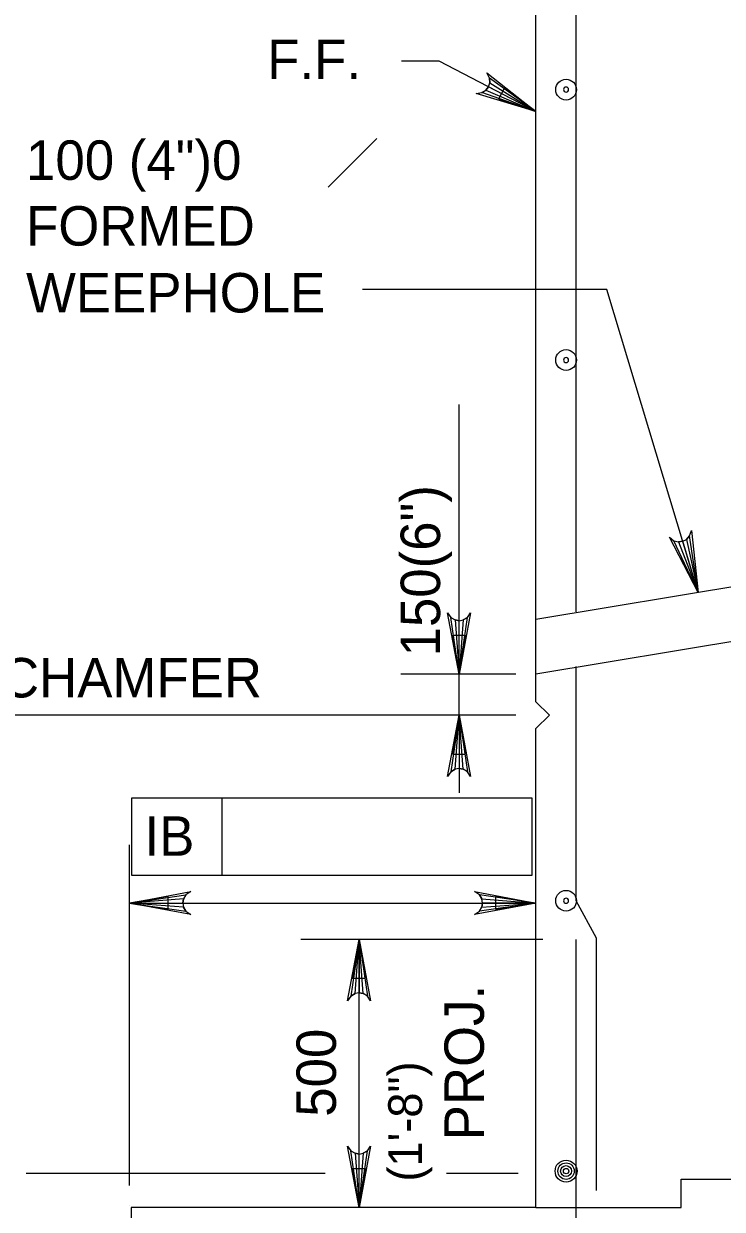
# Model space of a CAD drawing. Extents: x 638340 to 640241, y 295465 to 298435.
# Drawn here: x 639055.2 to 639108.3, y 297631.5 to 297721.6 of the extents above; entities that cross this region are included whole.
import ezdxf

# ---------------------------------------------------------------- set-up
doc = ezdxf.new("R2010")
doc.units = 0
for name, color, linetype in [('3', 7, 'Continuous'), ('4', 7, 'Continuous'), ('5', 7, 'Continuous'), ('6', 7, 'Continuous'), ('7', 7, 'Continuous'), ('9', 7, 'Continuous')]:
    doc.layers.add(name, color=color, linetype=linetype)

# ---------------------------------------------------------------- blocks, each defined once
blk = doc.blocks.new('B')
at = {"layer": '3'}
blk.add_circle((0, 0), 0.16, dxfattribs=at)
for start, end in [(0, 180), (180, 0)]:
    blk.add_arc((0, 0), 0.0391, start, end, dxfattribs=at)

msp = doc.modelspace()

# ---------------------------------------------------------------- linework, layer by layer
at = {"layer": '3'}
for p, q in [((639086.814, 297718.756), (639083.955, 297718.756)), ((639094.166, 297714.945), (639086.814, 297718.756)), ((639078.382, 297709.182), (639082.07, 297712.87)), ((639088.328, 297672.152), (639088.328, 297692.661)), ((639088.328, 297675.104), (639088.328, 297678.058)), ((639092.628, 297672.152), (639083.899, 297672.152)), ((639088.328, 297669.031), (639088.328, 297672.152)), ((639092.628, 297669.031), (639042.903, 297669.031)), ((639087.607, 297669.031), (639083.899, 297669.031)), ((639088.328, 297669.031), (639088.328, 297663.126)), ((639063.465, 297662.758), (639093.843, 297662.758)), ((639063.465, 297656.853), (639063.465, 297662.758)), ((639070.311, 297656.853), (639070.311, 297662.758)), ((639093.843, 297662.758), (639093.843, 297656.853)), ((639093.843, 297656.853), (639063.465, 297656.853)), ((639094.678, 297651.978), (639076.301, 297651.978)), ((639080.73, 297631.6), (639080.73, 297651.978)), ((639078.157, 297634.174), (639055.421, 297634.174)), ((639092.816, 297634.174), (639087.378, 297634.174))]:
    msp.add_line(p, q, dxfattribs=at)
for points in [[(639094.166, 297714.945), (639089.626, 297716.314), (639090.059, 297716.37), (639090.368, 297716.562), (639090.56, 297716.814), (639090.655, 297717.116), (639090.635, 297717.479), (639090.43, 297717.866), (639094.166, 297714.945), (639090.635, 297717.479), (639090.655, 297717.116), (639094.166, 297714.945), (639090.56, 297716.814), (639090.368, 297716.562), (639094.166, 297714.945), (639090.059, 297716.37)], [(639088.328, 297672.152), (639087.455, 297676.812), (639087.703, 297676.454), (639088.016, 297676.269), (639088.328, 297676.214), (639088.641, 297676.269), (639088.953, 297676.454), (639089.201, 297676.812), (639088.328, 297672.152), (639088.953, 297676.454), (639088.641, 297676.269), (639088.328, 297672.152), (639088.328, 297676.214), (639088.016, 297676.269), (639088.328, 297672.152), (639087.703, 297676.454)], [(639088.328, 297669.031), (639089.201, 297664.37), (639088.953, 297664.728), (639088.641, 297664.914), (639088.328, 297664.968), (639088.016, 297664.914), (639087.703, 297664.728), (639087.455, 297664.37), (639088.328, 297669.031), (639087.703, 297664.728), (639088.016, 297664.914), (639088.328, 297669.031), (639088.328, 297664.968), (639088.641, 297664.914), (639088.328, 297669.031), (639088.953, 297664.728)], [(639063.269, 297654.743), (639067.929, 297655.616), (639067.571, 297655.368), (639067.386, 297655.055), (639067.331, 297654.743), (639067.386, 297654.43), (639067.571, 297654.118), (639067.929, 297653.87), (639063.269, 297654.743), (639067.571, 297654.118), (639067.386, 297654.43), (639063.269, 297654.743), (639067.331, 297654.743), (639067.386, 297655.055), (639063.269, 297654.743), (639067.571, 297655.368)], [(639094.166, 297654.743), (639089.505, 297653.87), (639089.864, 297654.118), (639090.049, 297654.43), (639090.103, 297654.743), (639090.049, 297655.055), (639089.864, 297655.368), (639089.505, 297655.616), (639094.166, 297654.743), (639089.864, 297655.368), (639090.049, 297655.055), (639094.166, 297654.743), (639090.103, 297654.743), (639090.049, 297654.43), (639094.166, 297654.743), (639089.864, 297654.118)], [(639080.73, 297651.978), (639081.603, 297647.317), (639081.355, 297647.676), (639081.042, 297647.861), (639080.73, 297647.915), (639080.417, 297647.861), (639080.105, 297647.676), (639079.857, 297647.317), (639080.73, 297651.978), (639080.105, 297647.676), (639080.417, 297647.861), (639080.73, 297651.978), (639080.73, 297647.915), (639081.042, 297647.861), (639080.73, 297651.978), (639081.355, 297647.676)], [(639080.73, 297631.6), (639079.857, 297636.26), (639080.105, 297635.902), (639080.417, 297635.717), (639080.73, 297635.663), (639081.042, 297635.717), (639081.355, 297635.902), (639081.603, 297636.26), (639080.73, 297631.6), (639081.355, 297635.902), (639081.042, 297635.717), (639080.73, 297631.6), (639080.73, 297635.663), (639080.417, 297635.717), (639080.73, 297631.6), (639080.105, 297635.902)]]:
    msp.add_lwpolyline(points, dxfattribs=at)
for points in [[(639091.77, 297716.741), (639091.318, 297715.868), (639094.166, 297714.945)], [(639087.836, 297675.104), (639088.82, 297675.104), (639088.328, 297672.152)], [(639087.836, 297666.079), (639088.82, 297666.079), (639088.328, 297669.031)], [(639080.236, 297649.026), (639081.222, 297649.026), (639080.73, 297651.978)], [(639080.236, 297634.552), (639081.222, 297634.552), (639080.73, 297631.6)]]:
    msp.add_lwpolyline(points, close=True, dxfattribs=at)
at = {"layer": '4'}
for p, q in [((639099.539, 297701.391), (639080.988, 297701.391)), ((639106.487, 297678.362), (639099.539, 297701.391)), ((639063.269, 297633.267), (639063.269, 297659.172)), ((639063.269, 297654.743), (639094.166, 297654.743))]:
    msp.add_line(p, q, dxfattribs=at)
msp.add_lwpolyline([(639106.487, 297678.362), (639104.304, 297682.571), (639104.646, 297682.3), (639105, 297682.213), (639105.314, 297682.252), (639105.598, 297682.394), (639105.844, 297682.661), (639105.977, 297683.077), (639106.487, 297678.362), (639105.844, 297682.661), (639105.598, 297682.394), (639106.487, 297678.362), (639105.314, 297682.252), (639105, 297682.213), (639106.487, 297678.362), (639104.646, 297682.3)], dxfattribs=at)
for points in [[(639066.221, 297654.251), (639066.221, 297655.234), (639063.269, 297654.743)], [(639091.118, 297654.251), (639091.118, 297655.234), (639094.072, 297654.743)]]:
    msp.add_lwpolyline(points, close=True, dxfattribs=at)
at = {"layer": '5'}
for p, q in [((639097.231, 297676.887), (639097.231, 297750.853)), ((639097.231, 297654.909), (639097.231, 297672.731)), ((639098.768, 297652.067), (639097.231, 297654.909)), ((639097.231, 297602.805), (639097.231, 297651.978)), ((639098.768, 297632.881), (639098.768, 297652.067))]:
    msp.add_line(p, q, dxfattribs=at)
for radius in [0.833, 0.625, 0.417, 0.208]:
    msp.add_circle((639096.454, 297634.362), radius, dxfattribs=at)
at = {"layer": '6'}
msp.add_lwpolyline([(639094.166, 297631.6), (639105.198, 297631.6), (639105.198, 297633.762), (639112.39, 297633.762), (639112.39, 297631.6), (639124.04, 297631.6)], dxfattribs=at)
at = {"layer": '7'}
for p, q in [((639094.072, 297654.743), (639094.072, 297654.743)), ((639063.269, 297631.727), (639063.269, 297631.727)), ((639094.072, 297631.592), (639094.072, 297631.592))]:
    msp.add_line(p, q, dxfattribs=at)
at = {"layer": '9'}
for p, q in [((639094.166, 297670.058), (639094.166, 297767.854)), ((639119.957, 297680.606), (639094.166, 297676.308)), ((639137.282, 297679.337), (639094.166, 297672.152)), ((639094.166, 297670.058), (639095.191, 297669.031)), ((639094.166, 297668.006), (639095.191, 297669.031)), ((639094.166, 297631.6), (639094.166, 297668.006)), ((639063.406, 297631.6), (639063.406, 297600.188)), ((639094.166, 297631.6), (639063.406, 297631.6))]:
    msp.add_line(p, q, dxfattribs=at)

# ---------------------------------------------------------------- block references
at = {"layer": '3', "xscale": 4.921475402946, "yscale": 4.921475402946, "rotation": 90}
for p in [(639096.454, 297716.597), (639096.454, 297696.038), (639096.454, 297654.922)]:
    msp.add_blockref('B', p, dxfattribs=at)

# ---------------------------------------------------------------- texts
at = {"layer": '3'}
for s, height, p in [('F.F.', 3.0001, (639073.744, 297717.398)), ('100 (4")0', 3.0001, (639055.418, 297709.737)), ('FORMED', 3.0001, (639055.418, 297704.737)), ('WEEPHOLE', 3.0001, (639055.418, 297699.653)), ('20 (3/4")CHAMFER', 3.00014, (639038.265, 297670.381)), ('IB', 3.0001, (639064.421, 297658.339))]:
    msp.add_text(s, height=height, dxfattribs=at).set_placement(p)
for s, height, p in [('150(6")', 3.0001, (639086.882, 297673.5)), ('PROJ.', 3.0001, (639090.212, 297636.708)), ('500', 3.0001, (639078.967, 297638.496)), ('(1\'-8")', 2.5722, (639085.511, 297633.565))]:
    msp.add_text(s, height=height, rotation=90, dxfattribs=at).set_placement(p)

doc.saveas('drawing.dxf')
